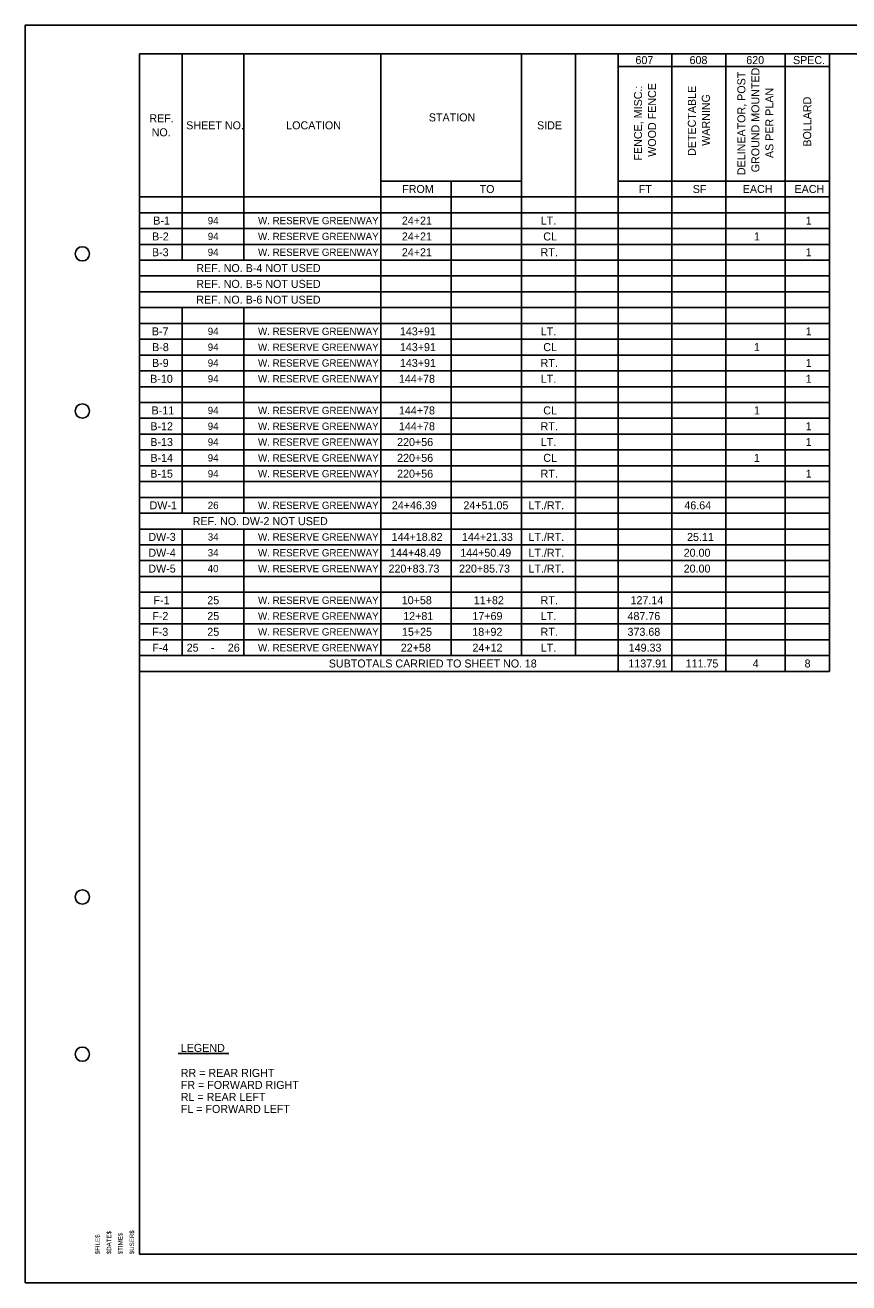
# Model space of a CAD drawing. Extents: x -16 to 102, y -13 to 9.
# Drawn here: x -16.37 to -1.97, y -12.91 to 9.09 of the extents above; entities that cross this region are included whole.
import ezdxf

# ---------------------------------------------------------------- set-up
doc = ezdxf.new("R2010")
doc.units = 0
for name, color, linetype in [('PV_P_EOP', 7, 'Continuous'), ('SH_Border', 7, 'Continuous'), ('SH_Cut_Line', 7, 'Continuous'), ('TX_P_1', 7, 'Continuous'), ('TX_P_Misc', 7, 'Continuous')]:
    doc.layers.add(name, color=color, linetype=linetype)

msp = doc.modelspace()

# ---------------------------------------------------------------- linework, layer by layer
at = {"layer": 'SH_Border'}
msp.add_lwpolyline([(-14.371, 8.593), (17.129, 8.593), (17.129, -12.407), (-14.371, -12.407)], close=True, dxfattribs=at)
for centre in [(-15.371, 5.093), (-15.371, 2.343), (-15.371, -6.157), (-15.371, -8.907)]:
    msp.add_circle(centre, 0.125, dxfattribs=at)
at = {"layer": 'SH_Cut_Line'}
msp.add_lwpolyline([(-16.371, -12.907), (17.629, -12.907), (17.629, 9.093), (-16.371, 9.093)], close=True, dxfattribs=at)
at = {"layer": 'TX_P_1'}
for p, q in [((-14.371, 8.593), (-2.308, 8.593)), ((-14.371, 8.593), (-14.371, -1.934)), ((-13.624, 8.593), (-13.624, 4.982)), ((-12.545, 8.593), (-12.545, 4.982)), ((-10.152, 8.593), (-10.152, -1.934)), ((-7.69, 8.593), (-7.69, -1.934)), ((-6.749, 8.593), (-6.749, -1.934)), ((-6.002, 8.593), (-6.002, -2.211)), ((-5.061, 8.593), (-5.061, -2.211)), ((-4.12, 8.593), (-4.12, -2.211)), ((-3.083, 8.593), (-3.083, -2.211)), ((-2.308, 8.593), (-2.308, -2.211)), ((-6.002, 8.372), (-2.308, 8.372)), ((-10.152, 6.366), (-7.69, 6.366)), ((-8.921, 6.366), (-8.921, -1.934)), ((-6.002, 6.366), (-2.308, 6.366)), ((-14.371, 6.089), (-2.308, 6.089)), ((-14.371, 5.812), (-2.308, 5.812)), ((-14.371, 5.536), (-2.308, 5.536)), ((-14.371, 5.259), (-2.308, 5.259)), ((-14.371, 4.982), (-2.308, 4.982)), ((-14.371, 4.706), (-2.308, 4.706)), ((-14.371, 4.429), (-2.308, 4.429)), ((-14.371, 4.152), (-2.308, 4.152)), ((-13.624, 4.152), (-13.624, 0.556)), ((-12.545, 4.152), (-12.545, 0.556)), ((-14.371, 3.876), (-2.308, 3.876)), ((-14.371, 3.599), (-2.308, 3.599)), ((-14.371, 3.322), (-2.308, 3.322)), ((-14.371, 3.046), (-2.308, 3.046)), ((-14.371, 2.769), (-2.308, 2.769)), ((-14.371, 2.492), (-2.308, 2.492)), ((-14.371, 2.216), (-2.308, 2.216)), ((-14.371, 1.939), (-2.308, 1.939)), ((-14.371, 1.662), (-2.308, 1.662)), ((-14.371, 1.386), (-2.308, 1.386)), ((-14.371, 1.109), (-2.308, 1.109)), ((-14.371, 0.832), (-2.308, 0.832)), ((-14.371, 0.556), (-2.308, 0.556)), ((-14.371, 0.279), (-2.308, 0.279)), ((-13.624, 0.279), (-13.624, -1.934)), ((-12.545, 0.279), (-12.545, -1.934)), ((-14.371, 0.002), (-2.308, 0.002)), ((-14.371, -0.274), (-2.308, -0.274)), ((-14.371, -0.551), (-2.308, -0.551)), ((-14.371, -0.828), (-2.308, -0.828)), ((-14.371, -1.104), (-2.308, -1.104)), ((-14.371, -1.381), (-2.308, -1.381)), ((-14.371, -1.658), (-2.308, -1.658)), ((-14.371, -1.934), (-2.308, -1.934)), ((-14.371, -1.934), (-14.371, -2.211)), ((-14.371, -2.211), (-2.308, -2.211)), ((-13.694, -8.897), (-12.811, -8.897))]:
    msp.add_line(p, q, dxfattribs=at)

# ---------------------------------------------------------------- texts
at = {"layer": 'PV_P_EOP'}
for s, p in [('REF.', (-14.199, 7.394)), ('STATION', (-9.312, 7.409)), ('NO.', (-14.159, 7.149)), ('SHEET NO.', (-13.555, 7.271)), ('LOCATION', (-11.806, 7.271)), ('SIDE', (-7.42, 7.271)), ('FROM', (-9.778, 6.157)), ('TO', (-8.424, 6.157)), (' SUBTOTALS CARRIED TO SHEET NO.', (-11.114, -2.143)), ('18', (-7.634, -2.143))]:
    msp.add_text(s, height=0.14, dxfattribs=at).set_placement(p)
at = {"layer": 'TX_P_1'}
for s, height, p in [('607', 0.14, (-5.699, 8.412)), ('608', 0.14, (-4.753, 8.412)), ('620', 0.14, (-3.761, 8.412)), ('SPEC.', 0.14, (-2.944, 8.412)), ('FT', 0.14, (-5.642, 6.157)), ('SF', 0.14, (-4.697, 6.157)), ('EACH', 0.14, (-3.823, 6.157)), ('EACH', 0.14, (-2.917, 6.157)), ('B-1', 0.14, (-14.131, 5.604)), ('94', 0.1273, (-13.178, 5.611)), ('W. RESERVE GREENWAY', 0.12727, (-12.299, 5.611)), ('24+21', 0.14, (-9.784, 5.604)), ('LT.', 0.14, (-7.355, 5.604)), ('1', 0.14, (-2.722, 5.604)), ('B-2', 0.14, (-14.152, 5.327)), ('94', 0.1273, (-13.178, 5.334)), ('W. RESERVE GREENWAY', 0.12727, (-12.299, 5.334)), ('24+21', 0.14, (-9.784, 5.327)), ('CL', 0.14, (-7.311, 5.327)), ('1', 0.14, (-3.628, 5.327)), ('B-3', 0.14, (-14.154, 5.051)), ('94', 0.1273, (-13.178, 5.057)), ('W. RESERVE GREENWAY', 0.12727, (-12.299, 5.057)), ('24+21', 0.14, (-9.784, 5.051)), ('RT.', 0.14, (-7.358, 5.051)), ('1', 0.14, (-2.722, 5.051)), ('REF. NO. B-4 NOT USED', 0.14, (-13.378, 4.774)), ('REF. NO. B-5 NOT USED', 0.14, (-13.378, 4.497)), ('REF. NO. B-6 NOT USED', 0.14, (-13.379, 4.221)), ('B-7', 0.14, (-14.156, 3.667)), ('94', 0.1273, (-13.178, 3.674)), ('W. RESERVE GREENWAY', 0.12727, (-12.299, 3.674)), ('143+91', 0.14, (-9.818, 3.667)), ('LT.', 0.14, (-7.355, 3.667)), ('1', 0.14, (-2.722, 3.667)), ('B-8', 0.14, (-14.151, 3.391)), ('94', 0.1273, (-13.178, 3.397)), ('W. RESERVE GREENWAY', 0.12727, (-12.299, 3.397)), ('143+91', 0.14, (-9.818, 3.391)), ('CL', 0.14, (-7.311, 3.391)), ('1', 0.14, (-3.628, 3.391)), ('B-9', 0.14, (-14.153, 3.114)), ('94', 0.1273, (-13.178, 3.12)), ('W. RESERVE GREENWAY', 0.12727, (-12.299, 3.12)), ('143+91', 0.14, (-9.818, 3.114)), ('RT.', 0.14, (-7.358, 3.114)), ('1', 0.14, (-2.722, 3.114)), ('B-10', 0.14, (-14.185, 2.837)), ('94', 0.1273, (-13.178, 2.844)), ('W. RESERVE GREENWAY', 0.12727, (-12.299, 2.844)), ('144+78', 0.14, (-9.835, 2.837)), ('LT.', 0.14, (-7.355, 2.837)), ('1', 0.14, (-2.722, 2.837)), ('B-11', 0.14, (-14.161, 2.284)), ('144+78', 0.14, (-9.835, 2.284)), ('CL', 0.14, (-7.311, 2.284)), ('1', 0.14, (-3.628, 2.284)), ('94', 0.1273, (-13.178, 2.29)), ('W. RESERVE GREENWAY', 0.12727, (-12.299, 2.29)), ('B-12', 0.14, (-14.182, 2.007)), ('94', 0.1273, (-13.178, 2.014)), ('W. RESERVE GREENWAY', 0.12727, (-12.299, 2.014)), ('144+78', 0.14, (-9.835, 2.007)), ('RT.', 0.14, (-7.358, 2.007)), ('1', 0.14, (-2.722, 2.007)), ('B-13', 0.14, (-14.183, 1.731)), ('94', 0.1273, (-13.178, 1.737)), ('W. RESERVE GREENWAY', 0.12727, (-12.299, 1.737)), ('220+56', 0.14, (-9.867, 1.731)), ('LT.', 0.14, (-7.355, 1.731)), ('1', 0.14, (-2.722, 1.731)), ('B-14', 0.14, (-14.181, 1.454)), ('94', 0.1273, (-13.178, 1.46)), ('W. RESERVE GREENWAY', 0.12727, (-12.299, 1.46)), ('220+56', 0.14, (-9.867, 1.454)), ('CL', 0.14, (-7.311, 1.454)), ('1', 0.14, (-3.628, 1.454)), ('B-15', 0.14, (-14.183, 1.177)), ('94', 0.1273, (-13.178, 1.184)), ('W. RESERVE GREENWAY', 0.12727, (-12.299, 1.184)), ('220+56', 0.14, (-9.867, 1.177)), ('RT.', 0.14, (-7.358, 1.177)), ('1', 0.14, (-2.722, 1.177)), ('DW-1', 0.14, (-14.195, 0.624)), ('26', 0.1273, (-13.178, 0.63)), ('W. RESERVE GREENWAY', 0.12727, (-12.299, 0.63)), ('24+46.39', 0.14, (-9.959, 0.624)), ('24+51.05', 0.14, (-8.707, 0.624)), ('LT./RT.', 0.14, (-7.57, 0.624)), ('46.64', 0.14, (-4.844, 0.624)), ('REF. NO. DW-2 NOT USED', 0.14, (-13.441, 0.347)), ('DW-3', 0.14, (-14.217, 0.071)), ('34', 0.1273, (-13.178, 0.077)), ('W. RESERVE GREENWAY', 0.12727, (-12.299, 0.077)), ('144+18.82', 0.14, (-9.962, 0.071)), ('144+21.33', 0.14, (-8.733, 0.071)), ('LT./RT.', 0.14, (-7.57, 0.071)), ('25.11', 0.14, (-4.796, 0.071)), ('DW-4', 0.14, (-14.216, -0.206)), ('34', 0.1273, (-13.178, -0.2)), ('W. RESERVE GREENWAY', 0.12727, (-12.299, -0.2)), ('144+48.49', 0.14, (-9.989, -0.206)), ('144+50.49', 0.14, (-8.763, -0.206)), ('LT./RT.', 0.14, (-7.57, -0.206)), ('20.00', 0.14, (-4.856, -0.206)), ('DW-5', 0.14, (-14.217, -0.483)), ('40', 0.1273, (-13.18, -0.476)), ('W. RESERVE GREENWAY', 0.12727, (-12.299, -0.476)), ('220+83.73', 0.14, (-10.017, -0.483)), ('220+85.73', 0.14, (-8.784, -0.483)), ('LT./RT.', 0.14, (-7.57, -0.483)), ('20.00', 0.14, (-4.856, -0.483)), ('F-1', 0.14, (-14.127, -1.036)), ('25', 0.14, (-13.186, -1.036)), ('W. RESERVE GREENWAY', 0.12727, (-12.299, -1.03)), ('10+58', 0.14, (-9.786, -1.036)), ('11+82', 0.14, (-8.526, -1.036)), ('RT.', 0.14, (-7.358, -1.036)), ('127.14', 0.14, (-5.785, -1.036)), ('F-2', 0.14, (-14.148, -1.313)), ('25', 0.14, (-13.186, -1.313)), ('W. RESERVE GREENWAY', 0.12727, (-12.299, -1.306)), ('12+81', 0.14, (-9.76, -1.313)), ('17+69', 0.14, (-8.551, -1.313)), ('LT.', 0.14, (-7.355, -1.313)), ('487.76', 0.14, (-5.838, -1.313)), ('F-3', 0.14, (-14.15, -1.589)), ('25', 0.14, (-13.186, -1.589)), ('W. RESERVE GREENWAY', 0.12727, (-12.299, -1.583)), ('15+25', 0.14, (-9.782, -1.589)), ('18+92', 0.14, (-8.552, -1.589)), ('RT.', 0.14, (-7.358, -1.589)), ('373.68', 0.14, (-5.838, -1.589)), ('F-4', 0.14, (-14.148, -1.866)), ('25', 0.14, (-13.546, -1.866)), ('26', 0.14, (-12.827, -1.866)), ('W. RESERVE GREENWAY', 0.12727, (-12.299, -1.86)), ('22+58', 0.14, (-9.803, -1.866)), ('24+12', 0.14, (-8.55, -1.866)), ('LT.', 0.14, (-7.355, -1.866)), ('149.33', 0.14, (-5.817, -1.866)), ('-', 0.14, (-13.124, -1.866)), ('1137.91', 0.14, (-5.823, -2.143)), ('111.75', 0.14, (-4.822, -2.143)), ('4', 0.14, (-3.648, -2.143)), ('8', 0.14, (-2.741, -2.143)), ('LEGEND', 0.14, (-13.65, -8.867)), ('RR = REAR RIGHT', 0.14, (-13.65, -9.305)), ('FR = FORWARD RIGHT', 0.14, (-13.65, -9.515)), ('RL = REAR LEFT', 0.14, (-13.65, -9.725)), ('FL = FORWARD LEFT', 0.14, (-13.65, -9.935))]:
    msp.add_text(s, height=height, dxfattribs=at).set_placement(p)
for s, p in [('GROUND MOUNTED,', (-3.532, 6.519)), ('DELINEATOR, POST', (-3.777, 6.469)), ('FENCE, MISC.:', (-5.584, 6.725)), ('WOOD FENCE', (-5.339, 6.79)), ('DETECTABLE', (-4.643, 6.805)), ('AS PER PLAN', (-3.287, 6.768)), ('WARNING', (-4.398, 6.982)), ('BOLLARD', (-2.626, 6.968))]:
    msp.add_text(s, height=0.14, rotation=90, dxfattribs=at).set_placement(p)
at = {"layer": 'TX_P_Misc'}
for s, p in [('$FILE$', (-15.067, -12.407)), ('$DATE$', (-14.867, -12.407)), ('$TIME$', (-14.667, -12.407)), ('$USER$', (-14.467, -12.407))]:
    msp.add_text(s, height=0.078, rotation=90, dxfattribs=at).set_placement(p)

doc.saveas('drawing.dxf')
